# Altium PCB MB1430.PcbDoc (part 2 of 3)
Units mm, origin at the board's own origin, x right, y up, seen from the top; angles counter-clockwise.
Board outline 18.54 x 50.29 mm, 4 copper layers (Top Layer, Signal Layer 1, Signal Layer 2, Bottom Layer), stack 1.614 mm thick; 124 components, 85 nets, 561 pads, 241 vias.
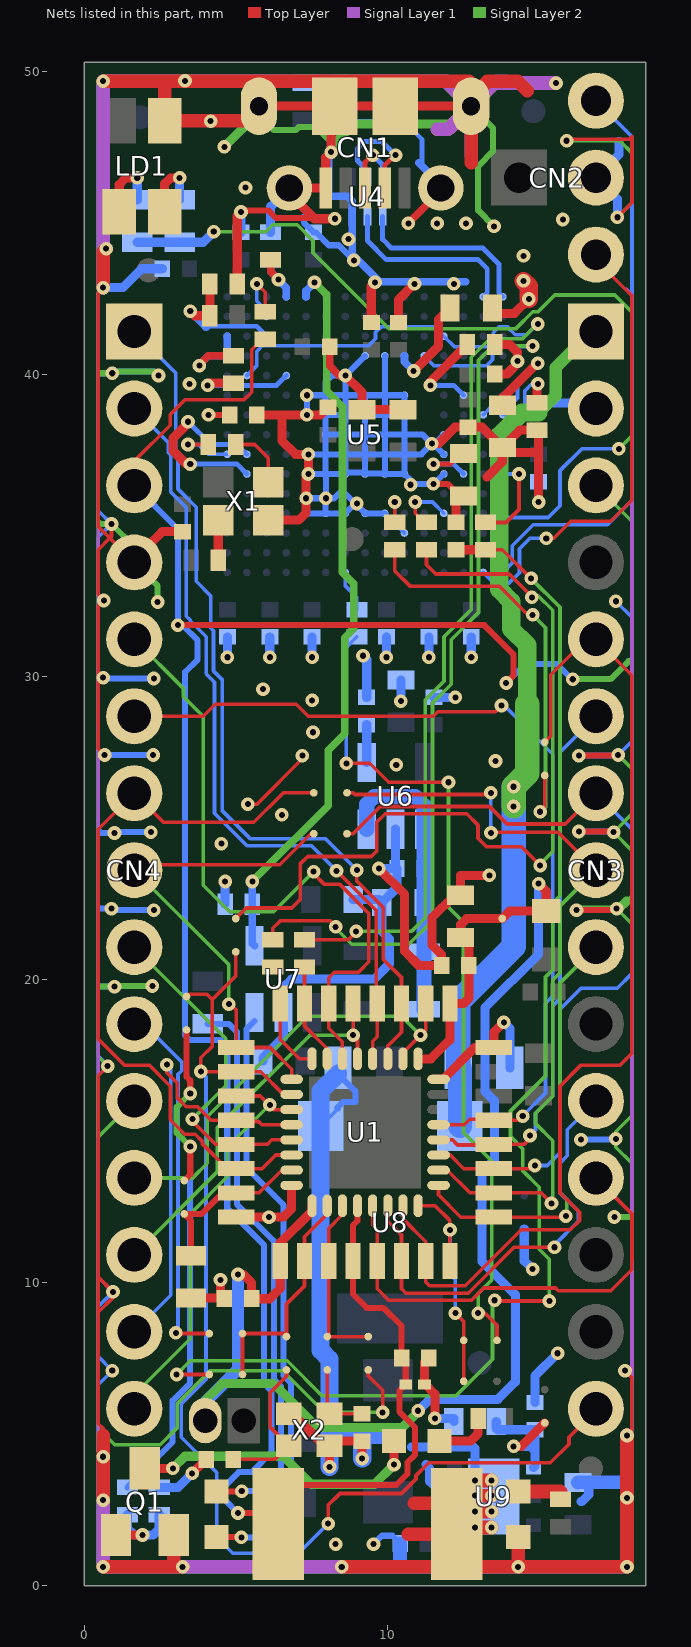
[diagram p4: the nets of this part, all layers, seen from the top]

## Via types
v1: diameter 0.45, hole 0.2, Top Layer to Bottom Layer, tented both sides, 241 vias

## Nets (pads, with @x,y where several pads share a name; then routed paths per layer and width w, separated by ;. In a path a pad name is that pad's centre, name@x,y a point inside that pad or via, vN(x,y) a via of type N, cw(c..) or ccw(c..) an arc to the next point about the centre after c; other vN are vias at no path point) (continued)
GND: B1.2 C1.1 C2.1 C3.1 C4.1 C5.1 C6.1 C7.1 C8.1 C9.1 C10.1 C11.1 C12.1 C13.1 C14.1 C15.1 C16.1 C19.1 C20.1 C21.1 C22.1 C23.1 C24.1 C25.1 C26.1 C27.1 C28.1 C29.1 C30.1 C31.1 C32.1 C33.1 C34.1 C35.1 C36.1 C37.1 C38.1 C39.1 C40.1 C41.1 C42.1 C43.1 C44.1 C45.1 C46.1 C47.1 CN1.5 CN1.6 CN1.7 CN1.8 CN1.9 CN1.10 CN1.11 CN2.3 CN3.2 CN4.4 LD1.1 LD4.2 Q1.2 R2.1 R5.1 R6.1 R7.1 R15.1 R20.1 R22.1 R24.1 SB16.1 U1.16 U1.32 U2.2 U3.2 U4.3 U5.D5 U5.D6 U5.D7 U5.D8 U5.D9 U5.F2 U5.F6 U5.F7 U5.F8 U5.F9 U5.F10 U5.F12 U5.G2 U5.G6 U5.G7 U5.G8 U5.G9 U5.G10 U5.G12 U5.H6 U5.H7 U5.H8 U5.H9 U5.H10 U5.H12 U5.J6 U5.J7 U5.J8 U5.J9 U5.J10 U5.K6 U5.K7 U5.K8 U5.K9 U5.K10 U5.M1 U5.M8 U5.M9 U5.N1 U6.2 U7.2 U8.1 U9.2 U9.EP X1.2 X2.2 X2.4 | length 685.2
  Top Layer w0.12: 0.46,8.825 0.46,10.19 ; 0.625,4.959 0.625,5.192 0.466,5.351 0.466,9.032 0.95,9.516 v1(0.95,9.7) 0.46,10.19 ; v1(0.625,42.85) 0.466,42.691 0.466,34.967 0.846,34.587 ; v1(0.675,27.425) 0.466,27.634 0.466,32.341 v1(0.65,32.525) 0.46,32.715 0.46,34.2 0.846,34.587 ; v1(0.775,17.151) 0.46,16.836 0.46,10.19 ; v1(0.9,35.05) 0.9,34.64 0.846,34.587 ; CN4.4@1.651,33.782 0.846,34.587 ; v1(5.4,25.8) 5.7,25.8 7.2,27.3 v1(7.2,27.4) ; v1(15.925,47.7) 15.975,47.75 18.001,47.75 18.082,47.831 18.082,45.657 v1(17.6,45.175) ; v1(17.85,7.1) 18.076,6.874 18.076,5.118 v1(17.917,4.959)
  Top Layer w0.2: v1(5.175,45.35) 5.225,45.4 6.075,45.4 6.325,45.15 7.575,45.15 8.25,45.15 v1(8.275,45.125) ; X2.4@6.75,5.675 X2.4@6.811,5.675 ; X2.2@8.1,4.625 8.025,4.625 X2.2@8.175,4.775 ; v1(11.526,36.377) 11.998,36.377 12.4,35.975 C12.1@12.525,35.975 ; v1(16.25,22.3) 16.257,22.307 17.532,22.307 v1(17.575,22.35) ; v1(16.325,24.9) 17.45,24.9 v1(17.475,24.875) ; v1(16.325,27.4) 17.6,27.4 v1(17.625,27.425)
  Top Layer w0.25: v1(3.8,40.275) 3.8,40.3 4.1,40.6 R6.1@4.925,40.6 ; C4.1@8.1,40.9 8.1,40.275 8.425,39.95 v1(8.621,39.95) ; v1(10.7,44.975) 11.771,46.046 CN1.6@11.771,46.142
  Top Layer w0.3: CN4.4@1.651,33.782 1.651,33.876 2.575,34.8 C13.1@3.25,34.8 ; v1@3.425,37.025 3.375,37.025 2.93,37.47 2.93,37.88 3.425,38.375 v1(3.425,38.425) ; R15.1@3.525,9.5 C19.1@4.6,9.5 ; v1(3.56,3.71) C22.1@4.025,4.175 ; v1(4.5,10.1) 4.5,9.6 C19.1@4.6,9.5 ; C19.1@4.625,9.475 C19.1@4.6,9.5 ; U1.32@5.025,12.165 U1.32@5.021,12.169 v1(6.1,12.169) 6.569,12.169 6.846,12.446 U1.32@6.846,13.219 ; R2.1@5.05,42.975 5.05,45.225 v1(5.175,45.35) ; C11.1@5.7,38.65 6.525,38.65 ; CN1.8@5.771,48.842 CN1.11@8.271,48.842 CN1.10@10.271,48.842 CN1.9@12.771,48.842 ; X1.2@6.075,35.175 7.075,35.175 7.325,35.425 v1(7.325,35.9) 7.325,36.625 v1(7.4,36.7) v1(7.4,37.35) 6.975,37.35 6.525,37.8 6.525,38.65 ; X2.4@6.811,5.675 6.882,5.675 7.782,4.775 8.175,4.775 C21.1@9.175,4.775 ; C8.1@8.05,38.9 7.8,38.65 v1(7.35,38.65) 6.525,38.65 ; v1(8.1,3.925) X2.2@8.1,4.625 ; CN1.11@8.25,48.8 8.15,48.7 v1(8.15,47.325) 7.971,47.146 CN1.5@7.971,46.142 CN1.7@6.771,46.142 6.771,45.954 7.575,45.15 7.6,45.125 v1(8.275,45.125) ; v1(8.621,39.95) 9.175,39.396 C9.1@9.175,38.825 C10.1@10.525,38.825 ; v1(9.175,4.2) C21.1@9.175,4.775 ; C21.1@9.225,4.825 C21.1@9.175,4.775 ; C2.1@9.475,41.7 9.475,42.9 v1(9.6,43.025) ; v1(9.725,23.675) 10.575,22.825 10.575,20.95 11.05,20.475 C16.1@11.8,20.475 11.8,20.835 11.475,21.16 11.475,22.05 12.225,22.8 C15.1@12.425,22.8 12.425,23.45 v1(13.375,23.45) ; C3.1@10.375,41.7 10.375,42.45 v1(10.9,42.975) ; C20.1@11.375,7.525 11.237,7.387 U2.2@11.237,6.65 11.25,6.65 11.575,6.325 v1(11.575,5.525) ; v1(11.475,37.7) 11.694,37.7 12.244,38.25 C6.1@12.675,38.25 13.125,38.25 C7.1@13.8,37.575 ; U1.16@11.696,16.719 11.844,16.719 12.894,17.769 U1.16@13.521,17.769 13.521,18.271 v1(13.85,18.6) ; C14.1@12.275,35.1 12.275,35.85 C12.1@12.4,35.975 ; 13.3,36.6 13.8,37.1 C7.1@13.8,37.575 ; C1.1@13.475,42.175 13.65,42 14.2,42 v1(14.675,42.475) ; C5.1@13.55,40 13.955,40 14.38,40.425 v1(14.3,40.425) 14.3,40.725 14.05,40.975 R5.1@13.55,40.975 ; v1(15,35.775) 15,37.35 ; C7.1@13.8,37.575 14.375,38.15 R7.1@14.95,38.15 15,38.1 15,37.35 ; C7.1@13.8,37.575 13.963,37.412 14.938,37.412 15,37.35
  Top Layer w0.45: v1(0.625,0.625) 2.95,0.625 ; v1(0.625,2.825) v1(0.625,4.258) 0.625,4.959 ; v1(0.625,42.85) 0.625,44.04 v1(0.725,44.14) ; v1(0.625,49.667) 2.675,49.667 ; Q1.2@2.95,1.675 2.95,0.625 ; v1(3.25,0.625) 2.95,0.625 ; CN1.8@5.771,48.842 5.292,48.363 LD1.1@2.655,48.363 2.655,49.647 2.675,49.667 ; v1(8.5,0.625) 10.221,0.625 ; 10.7,1.7 11.965,1.7 B1.2@12.297,2.032 ; 10.9,2.725 11.604,2.725 B1.2@12.297,2.032 ; 11.253,0.625 10.221,0.625 ; B1.2@12.297,1.669 B1.2@12.297,2.032 ; 12.771,46.979 CN1.9@12.771,48.842 CN1.9@12.771,49.129 ; v1(13.449,1.924) v1(12.899,1.924) 12.405,1.924 B1.2@12.297,2.032 ; v1(13.449,2.449) v1(12.899,2.449) 12.714,2.449 B1.2@12.297,2.032 ; v1(13.449,2.974) v1(12.899,2.974) B1.2@12.399,2.974 ; v1(13.449,3.474) v1(12.899,3.474) B1.2@12.399,2.974 ; LD4.2@14.326,1.612 14.326,0.626 v1(14.325,0.625) ; 14.625,49.35 14.308,49.667 13.309,49.667 CN1.9@12.771,49.129 ; v1(17.917,4.959) v1(17.917,2.9) v1(17.917,0.625) v1(14.325,0.625) ; 2.675,49.667 12.7,49.667 12.771,49.596 CN1.9@12.771,49.129 ; 10.221,0.625 v1(14.325,0.625) ; B1.2@12.297,2.032 12.297,2.872 B1.2@12.399,2.974
  Top Layer w0.6: v1(14.5,43.075) 14.675,42.9 v1(14.675,42.475)
  Signal Layer 1 w0.12: v1(0.625,42.85) 0.46,42.685 0.46,4.44 0.625,4.275 v1@0.642,4.258 ; 17.9,42.8 18.082,42.618 18.082,6.775 18.076,6.769 18.076,5.118 v1(17.917,4.959)
  Signal Layer 1 w0.45: v1@0.625,4.275 v1(0.625,2.825) v1(0.625,0.625) v1(3.25,0.625) v1(8.5,0.625) v1(17.917,0.625) v1(17.917,2.9) v1(17.917,4.959) ; v1(0.625,42.85) v1(0.625,49.667) 11.946,49.667 CN1.9@12.771,48.842 ; 11.65,48.075 12.004,48.075 CN1.9@12.771,48.842 ; v1@15.567,49.608 13.537,49.608 CN1.9@12.771,48.842
  Signal Layer 2 w0.12: v1(0.625,42.85) 0.46,42.685 0.46,32.715 v1(0.65,32.525) 0.466,32.341 0.466,17.46 v1(0.775,17.151) ; v1(15.925,47.7) 17.675,47.7 18.082,47.293 18.082,45.657 v1(17.6,45.175) ; v1(17.575,22.35) 18.076,21.849 ; v1(17.625,27.425) 18.082,26.968 18.082,25.482 v1(17.475,24.875) 18.076,24.274 ; 17.9,22.6 18.076,22.776 ; v1(17.917,4.959) 18.076,5.118 18.076,13.953 17.55,14.479 v1(17.55,14.75) 17.55,14.985 18.076,15.511 18.076,21.849 ; 18.076,21.849 18.076,22.776 ; 18.076,22.776 18.082,22.782 18.082,24.268 18.076,24.274 ; 18.076,22.776 18.076,24.274
  Signal Layer 2 w0.2: 0.5,19.775 v1(1,19.775) 1.025,19.8 v1(2.25,19.8) ; 0.5,35.075 0.525,35.05 v1(0.9,35.05) 1.651,34.299 CN4.4@1.651,33.782 2.425,33.008 v1(2.425,32.475) ; 0.5,40.025 v1(0.925,40.025) 0.987,40.087 2.313,40.087 v1(2.45,39.95) ; CN1.8@5.771,48.842 5.771,48.646 5.771,48.538 6.259,48.05 6.975,48.05 7.075,48.15 7.65,48.15 8.15,47.65 8.15,47.5 v1(8.15,47.325) ; CN1.9@12.771,48.842 13.5,48.113 13.5,47.363 13,46.863 13,45.4 v1(13.525,44.875) ; v1(16.25,22.3) 16.3,22.35 v1(17.575,22.35) ; v1(17.5,12.175) 18.042,12.175
  Signal Layer 2 w0.3: v1(4.625,47.5) CN1.8@5.771,48.646 ; v1@8.15,47.5 8.9,48.25 12.328,48.25 12.771,48.693 CN1.9@12.771,48.842 ; v1(17.575,22.35) 17.65,22.35 17.9,22.6
  Signal Layer 2 w0.45: v1(0.625,4.258) v1(0.625,2.825) v1(0.625,0.625) v1(14.325,0.625) v1(17.917,0.625) v1(17.917,2.9) v1(17.917,4.959) ; v1(0.625,42.85) v1(0.625,49.667) 11.946,49.667 CN1.9@12.771,48.842 12.771,48.921 13.458,49.608 v1@15.567,49.608
  Bottom Layer w0.12: v1@0.46,32.475 0.46,34.61 v1(0.9,35.05) 0.46,35.49 0.46,40.09 ; 0.466,19.775 0.466,32.341 v1(0.65,32.525) ; 0.5,19.775 0.466,19.741 0.466,17.484 ; 0.525,40.025 0.46,40.09 ; v1(0.625,4.258) 0.46,4.423 0.46,6.635 ; v1(0.625,42.85) 0.46,42.685 0.46,40.09 ; v1(0.775,17.151) 0.799,17.151 0.466,17.484 ; U8.1@7.8,15.175 U8.1@8.375,15.75 ; v1(17.55,32.5) 18.082,31.968 18.082,27.882 v1(17.625,27.425) ; v1(17.85,7.1) 18.076,6.874 18.076,5.118 v1(17.917,4.959) ; 0.46,6.635 v1(0.925,7.1) 0.46,7.565 ; 0.46,6.635 0.46,7.565 ; 0.46,7.565 0.46,9.21 0.466,9.216 ; 0.466,9.216 v1(0.95,9.7) 0.466,10.184 ; 0.466,9.216 0.466,10.184 ; 0.466,10.184 0.466,17.484
  Bottom Layer w0.15: v1@8.15,47.55 8.65,48.05 8.7,48.05 9,48.35 10.55,48.35 11.15,47.75 11.15,46.925
  Bottom Layer w0.16: v1@3.425,37.025 5.046,37.025 U5.F2@5.371,36.7 ; v1(3.425,38.425) 4.175,37.675 5.046,37.675 U5.G2@5.371,37.35
  Bottom Layer w0.2: 0.5,19.775 v1(1,19.775) 1.025,19.8 v1(2.25,19.8) ; 0.5,22.375 0.525,22.35 v1(0.9,22.35) 0.943,22.307 2.293,22.307 v1(2.3,22.3) ; 0.5,24.9 0.55,24.85 v1(1,24.85) 1.025,24.875 v1(2.2,24.875) ; 0.525,40.025 v1(0.925,40.025) 0.987,40.087 2.313,40.087 v1(2.45,39.95) ; v1(0.625,29.975) 0.65,29.95 v1(2.3,29.95) ; v1(0.675,27.425) v1(2.275,27.425) ; 7.25,45.192 7.25,45 C24.1@7.575,44.675 7.651,44.675 8.076,44.25 8.4,44.25 v1(8.9,43.75) v1@8.975,43.825 ; v1(8.15,47.325) v1@8.15,47.55 ; U8.1@8.375,15.75 8.35,15.775 8.55,15.975 8.95,15.975 8.95,16.325 8.375,16.9 C42.1@8.375,17.1 ; v1@9,35.75 v1(9,35.727) ; v1(9,35.727) v1@9,35.75 ; U5.M8@9.271,40.6 v1(8.621,39.95) ; v1(9.55,1.375) 9.825,1.65 10.175,1.65 C47.1@10.425,1.4 ; U5.D9@9.921,35.4 U5.D8@9.271,35.4 9,35.671 v1(9,35.727) ; U5.M9@9.921,40.6 U5.K9@9.921,39.3 ; U5.F12@11.871,36.7 11.548,36.377 v1(11.526,36.377) 10.807,36.377 v1(10.775,36.345) 10.775,36.496 U5.F10@10.571,36.7 ; U5.G12@11.871,37.35 v1@11.521,37.7 ; U5.H12@11.871,38 11.571,37.7 v1@11.521,37.7 ; v1(16.25,22.3) 16.257,22.307 17.532,22.307 v1(17.575,22.35) ; v1(16.325,24.9) 17.45,24.9 v1(17.475,24.875) ; v1(16.325,27.4) 17.6,27.4 v1(17.625,27.425) ; v1(16.4,14.725) 17.525,14.725 v1(17.55,14.75) ; v1(7.325,35.9) 7.325,36.625 v1(7.4,36.7) ; v1(7.325,35.9) v1(7.975,35.9) ; v1(7.325,35.9) 7.321,35.896 U5.D5@7.321,35.4 U5.D6@7.971,35.4 ; v1(7.4,36.7) v1(7.4,37.35) U5.G6@7.971,37.35 ; v1(7.4,36.7) U5.F6@7.971,36.7 ; U5.D6@7.971,35.4 U5.D7@8.621,35.4 v1@8.948,35.727 ; U5.D6@7.971,35.4 7.971,35.896 v1(7.975,35.9) ; U5.F6@7.971,36.7 7.975,36.696 v1(7.975,35.9) ; U5.F6@7.971,36.7 U5.G6@7.971,37.35 ; U5.F6@7.971,36.7 U5.F7@8.621,36.7 ; U5.G6@7.971,37.35 U5.G7@8.621,37.35 ; U5.G6@7.971,37.35 U5.H6@7.971,38 ; U5.H6@7.971,38 U5.H7@8.621,38 ; U5.H6@7.971,38 U5.J6@7.971,38.65 ; U5.J6@7.971,38.65 U5.J7@8.621,38.65 ; U5.J6@7.971,38.65 U5.K6@7.971,39.3 ; U5.J6@7.971,38.65 v1(7.35,38.65) v1(7.35,39.3) U5.K6@7.971,39.3 ; U5.K6@7.971,39.3 U5.K7@8.621,39.3 ; U5.K6@7.971,39.3 7.971,39.75 8.171,39.95 v1(8.621,39.95) ; v1(7.975,35.9) 8.25,35.9 8.555,36.205 ; 8.555,36.205 8.555,36.116 8.944,35.727 v1@8.948,35.727 ; 8.555,36.205 8.555,36.634 U5.F7@8.621,36.7 ; U5.F7@8.621,36.7 U5.F7@8.621,36.745 ; U5.F7@8.621,36.745 U5.G7@8.621,37.35 ; U5.F7@8.621,36.745 9.226,36.745 U5.F8@9.271,36.7 U5.F8@9.271,36.72 ; U5.G7@8.621,37.35 U5.G8@9.271,37.35 ; U5.G7@8.621,37.35 U5.H7@8.621,38 ; U5.H7@8.621,38 U5.H8@9.271,38 ; U5.H7@8.621,38 U5.J7@8.621,38.65 ; U5.J7@8.621,38.65 U5.J8@9.271,38.65 ; U5.J7@8.621,38.65 U5.K7@8.621,39.3 ; U5.K7@8.621,39.3 v1(8.621,39.95) ; U5.K7@8.621,39.3 U5.K8@9.271,39.3 ; v1@8.948,35.727 v1(9,35.727) ; U5.F8@9.271,36.72 U5.G8@9.271,37.35 ; U5.F8@9.271,36.72 9.901,36.72 U5.F9@9.921,36.7 ; U5.G8@9.271,37.35 U5.G9@9.921,37.35 ; U5.G8@9.271,37.35 U5.H8@9.271,38 ; U5.H8@9.271,38 U5.H9@9.921,38 ; U5.H8@9.271,38 U5.J8@9.271,38.65 ; U5.J8@9.271,38.65 U5.J9@9.921,38.65 ; U5.J8@9.271,38.65 U5.K8@9.271,39.3 ; U5.K8@9.271,39.3 U5.K9@9.921,39.3 ; U5.F9@9.921,36.7 U5.G9@9.921,37.35 ; U5.F9@9.921,36.7 U5.F10@10.571,36.7 ; U5.G9@9.921,37.35 U5.G10@10.571,37.35 ; U5.G9@9.921,37.35 U5.H9@9.921,38 ; U5.H9@9.921,38 U5.H10@10.571,38 ; U5.H9@9.921,38 U5.J9@9.921,38.65 ; U5.J9@9.921,38.65 U5.J10@10.571,38.65 ; U5.J9@9.921,38.65 U5.K9@9.921,39.3 ; U5.K9@9.921,39.3 U5.K10@10.571,39.3 U5.J10@10.571,38.65 ; U5.F10@10.571,36.7 U5.G10@10.571,37.35 ; U5.G10@10.571,37.35 11.125,37.35 v1(11.475,37.7) ; U5.G10@10.571,37.35 U5.H10@10.571,38 ; U5.H10@10.571,38 11.171,38 11.471,37.7 v1(11.475,37.7) ; U5.H10@10.571,38 U5.J10@10.571,38.65 ; v1(11.475,37.7) v1@11.521,37.7
  Bottom Layer w0.25: v1(3.8,40.275) 3.8,40.3 4.1,40.6 U5.M1@4.721,40.6 U5.N1@4.721,41.25 ; v1(8.15,47.325) 8.075,47.25 8.075,45.875 8.675,45.875 8.85,45.7 U4.3@8.85,45.2 8.85,43.95 8.975,43.825 9.75,43.05 12.6,43.05 ; 11.05,46.98 11.771,46.259 CN1.6@11.771,46.142
  Bottom Layer w0.3: v1(0.625,42.85) 1.275,42.85 1.9,43.475 C26.1@2.575,43.475 ; R24.1@2.475,3.25 3.1,3.25 v1(3.56,3.71) ; R22.1@4.65,22.5 v1(4.65,23.25) ; v1(4.725,30.65) C34.1@4.725,31.325 ; C25.1@5.175,44.675 v1(5.175,45.35) ; C43.1@5.9,17.325 5.9,17.425 6.575,18.1 U7.2@6.575,18.925 6.575,19.75 6.85,20.025 9.575,20.025 10.075,20.525 10.075,21.35 9.825,21.6 C40.1@9.825,22.55 ; v1(6.125,30.65) C33.1@6.125,31.325 ; R20.1@6.15,44.675 6.15,45.521 CN1.7@6.771,46.142 ; v1(7.525,30.65) C32.1@7.525,31.325 ; C39.1@8.875,22.65 9.725,22.65 C40.1@9.825,22.55 ; v1(9.2,30.7) 9.325,30.575 C37.1@9.325,29.325 ; v1(9.725,23.675) C38.1@10.325,23.675 ; v1(9.975,30.65) C31.1@9.975,31.325 ; U6.2@10.275,24.975 10.275,23.725 C38.1@10.325,23.675 ; v1(10.45,29.2) C35.1@10.45,29.9 ; 10.8,4.575 12.85,4.575 12.899,4.526 v1(12.899,3.474) ; 11.275,4 11.4,3.875 11.4,3.45 11.9,2.95 U9.2@12.225,2.95 ; v1(11.375,30.65) C30.1@11.375,31.325 ; C36.1@11.55,29.325 v1(12.25,29.325) ; v1(11.575,5.525) 12.2,5.525 12.163,5.487 12.2,5.45 C45.1@12.2,5.425 ; v1(12.775,30.65) C29.1@12.775,31.325 ; v1(13.85,18.6) 14.05,18.4 C41.1@14.05,17.1 ; SB16.1@14.525,11.775 14.525,10.725 v1(14.8,10.45) ; C44.1@14.875,6.05 14.875,6.925 v1(15.625,7.675) ; v1(15,35.775) C28.1@15,36.45 ; C27.1@15,39.05 16.703,39.05 CN3.2@16.891,38.862 ; 16.4,2.775 16.422,2.775 16.655,3.008 16.655,3.288 C46.1@16.523,3.42 ; v1(17.6,45.175) 17.6,45.773 CN2.3@16.891,46.482 17.65,47.241 17.65,47.675 ; C40.1@9.825,22.55 10.325,23.05 C38.1@10.325,23.675
  Bottom Layer w0.45: v1(0.625,4.258) v1(0.625,2.825) v1(0.625,0.625) 10.375,0.625 ; v1(0.625,42.85) v1(0.625,49.667) C23.1@8.55,49.667 ; C23.1@8.475,49.65 8.533,49.65 C23.1@8.55,49.667 ; C47.1@10.425,1.4 10.425,0.675 10.375,0.625 ; U9.2@12.225,2.95 U9.EP@13.525,2.95 ; 12.771,47.204 CN1.9@12.771,48.842 ; CN1.9@12.771,49.048 CN1.9@12.771,48.9 ; 13.925,49.667 13.596,49.667 CN1.9@12.8,48.871 ; C46.1@16.292,3.408 16.292,3.42 16.523,3.42 17.897,3.42 17.917,3.4 ; v1@17.917,4.925 17.917,3.4 ; C23.1@8.55,49.667 12.004,49.667 CN1.9@12.771,48.9 ; 10.375,0.625 v1(14.325,0.625) v1(17.917,0.625) v1(17.917,2.9) 17.917,3.4 ; CN1.9@12.771,48.842 CN1.9@12.8,48.871 ; CN1.9@12.771,48.842 CN1.9@12.771,48.9 ; CN1.9@12.771,48.9 CN1.9@12.8,48.871
  Bottom Layer w0.6: v1(8.1,3.925) 8.1,4.975 ; C42.1@8.375,16.9 7.8,16.325 U8.1@7.8,15.175 7.8,7.775 8.1,7.475 8.1,4.975 ; v1(9.175,4.2) 9.175,4.95 9.2,4.975 ; 10.225,4.7 9.95,4.975 9.2,4.975 ; 8.1,4.975 9.2,4.975
  other v1: 8.3,1.375 4.525,24.5 6.525,25.45 10.3,27.1 13.575,27.225 7.55,28.175 7.525,29.225 5.9,29.6 3.5,37.025 3.475,39.675 12.2,42.975 14.5,43.9 8.725,44.45 11.65,44.975 12.6,44.975 15.8,45.1 5.325,46.15 4.175,48.35 15.575,49.6 3.325,49.675
GNDDetect: R5.2 U5.K13 | length 3.1
  Top Layer w0.3: v1(11.425,39.625) 11.425,39.75 R5.2@12.65,40.975
  Bottom Layer w0.16: v1(11.425,39.625) 12.196,39.625 U5.K13@12.521,39.3
NetC1_2: C1.2 U5.M10 | length 3.2
  Top Layer w0.3: v1(10.875,40.1) 11.7,40.925 11.7,41.8 C1.2@12.075,42.175
  Bottom Layer w0.25: U5.M10@10.571,40.6 10.571,40.404 v1(10.875,40.1)
NetC7_2: C7.2 U5.J14 | length 4.7
  Top Layer w0.3: C7.2@13.8,38.975 13.8,39.2 14.95,40.35 v1(14.975,40.35)
  Bottom Layer w0.12: U5.J14@13.171,38.65 13.496,38.975 14.075,38.975 14.3,39.2 14.3,39.675 v1(14.975,40.35)
NetC12_2: C12.2 U5.F13 | length 2.3
  Top Layer w0.16: v1(11.525,37.025) 12.075,37.025 12.425,37.375 C12.2@12.525,37.375
  Bottom Layer w0.16: v1(11.525,37.025) 12.196,37.025 U5.F13@12.521,36.7
NetC37_2: C37.2 U6.4 | length 1.3
  Bottom Layer w0.3: U6.4@9.325,27.175 C37.2@9.325,28.425
NetC38_2: C38.2 C40.2 D1.2 D2.2 U6.1 U6.3 | length 9.7
  Bottom Layer w0.5: U6.3@9.325,24.975 9.325,25.8 9.575,26.05 10.925,26.05 11.225,25.75 U6.1@11.225,24.975 C38.2@11.225,23.675 C40.2@11.225,22.55 11.22,22.545 D1.2@11.22,20.925 D2.2@11.22,19.025
NetC44_2: C44.2 C45.2 SB15.1 U9.4 | length 5.1
  Top Layer w0.3: v1(14.175,4.6) 14.425,4.6 SB15.1@15.2,5.375
  Bottom Layer w0.3: C45.2@13.6,5.425 13.6,5.2 13.65,5.15 C44.2@14.875,5.15 14.875,4.75 ; v1@14.175,4.625 v1(14.175,4.6) 14.725,4.6 ; U9.4@14.825,3.9 14.875,3.95 14.875,4.45 ; 14.725,4.6 14.875,4.75 ; 14.725,4.6 14.875,4.45 ; 14.875,4.45 14.875,4.75
NetLD1_2: LD1.2 R18.1 | length 2.2
  Top Layer w0.3: LD1.2@2.655,45.363 2.655,46.28 2.85,46.475 v1(3.15,46.475)
  Bottom Layer w0.3: R18.1@3.15,45.75 v1(3.15,46.475)
NetLD1_3: LD1.3 R19.1 | length 2.3
  Top Layer w0.3: LD1.3@1.155,45.363 1.155,46.255 1.375,46.475 v1(1.75,46.475)
  Bottom Layer w0.3: R19.1@1.75,45.75 v1(1.75,46.475)
NetLD2_1: LD2.1 R16.1 | length 1.9
  Top Layer w0.3: LD2.1@11.725,4.775 12.75,4.775 13,5.025 R16.1@13,5.525
NetLD2_2: LD2.2 Q1.3 | length 9.8
  Top Layer w0.3: Q1.3@2,3.875 v1(2.925,3.875) ; v1(10.225,4) LD2.2@10.225,4.775
  Signal Layer 2 w0.3: v1(2.925,3.875) 3.325,4.275 6.575,4.275 7.5,3.35 9.575,3.35 v1(10.225,4)
NetLD3_1: LD3.1 R23.2 | length 18.6
  Top Layer w0.2: LD3.1@4.369,3.112 5.187,3.112 v1(5.2,3.125)
  Bottom Layer w0.2: R23.2@4.075,18.55 4.775,18.55 5.04,18.285 5.04,12.6 6.26,11.38 6.26,6.812 6.5,6.572 6.5,3.695 5.93,3.125 v1(5.2,3.125)
NetLD3_2: LD3.2 U7.3 | length 19.9
  Top Layer w0.2: LD3.2@4.369,1.612 5.173,1.612 v1(5.185,1.6)
  Bottom Layer w0.2: v1(5.185,1.6) 6.225,1.6 6.82,2.195 6.82,6.705 6.58,6.945 6.58,12.57 5.36,13.79 5.36,18.385 U7.3@5.625,18.65
NetLD4_1: LD4.1 R17.1 | length 1.4
  Top Layer w0.45: LD4.1@14.326,3.112 15.713,3.112 R17.1@15.725,3.1
NetQ1_1: Q1.1 R24.2 R25.2 | length 3
  Top Layer w0.3: Q1.1@1.05,1.675 v1(1.925,1.675)
  Bottom Layer w0.3: R25.2@1.425,2.35 1.425,1.9 1.65,1.675 v1(1.925,1.675) 2.275,1.675 2.475,1.875 R24.2@2.475,2.35
NetR2_2: R2.2 R3.1 U5.N3 | length 4.7
  Top Layer w0.3: v1(3.5,42.075) 3.65,41.925 R3.1@4.15,41.925 R2.2@4.15,42.975
  Bottom Layer w0.16: 4.025,41.575 5.696,41.575 U5.N3@6.021,41.25
  Bottom Layer w0.3: v1(3.5,42.075) 3.5,42.1 4.025,41.575
NetR6_2: R6.2 U5.L4 | length 3.6
  Top Layer w0.3: v1(4.075,39.625) 4.15,39.7 R6.2@4.925,39.7
  Bottom Layer w0.16: v1(4.075,39.625) 6.346,39.625 U5.L4@6.671,39.95
NetR7_2: R7.2 U5.J15 | length 2.5
  Top Layer w0.3: R7.2@14.95,39.05 14.95,39.65 v1(14.975,39.675)
  Bottom Layer w0.12: U5.J15@13.821,38.65 13.821,38.655 14.226,38.655 14.54,38.969 14.54,39.44 14.775,39.675 v1(14.975,39.675)
NetR8_1: R8.1 X1.3 | length 2.1
  Top Layer w0.12: R8.1@5,37.675 5.625,37.675 6.075,37.225 X1.3@6.075,36.425
NetR8_2: R8.2 U5.G1 | length 2.1
  Top Layer w0.12: v1(3.425,37.675) R8.2@4.1,37.675
  Bottom Layer w0.12: v1(3.425,37.675) 3.775,37.675 4.1,37.35 U5.G1@4.721,37.35
NetR11_1: R11.1 U5.F15 | length 3
  Top Layer w0.12: R11.1@13.25,35.1 13.925,35.1 14.35,35.525 v1(14.35,36.7)
  Bottom Layer w0.12: U5.F15@13.821,36.7 v1(14.35,36.7)
NetR12_2: R12.2 X1.1 | length 1.3
  Top Layer w0.3: R12.2@4.425,33.85 X1.1@4.425,35.175
NetR25_1: R25.1 SB6.2 SB7.2 | length 17.6
  Top Layer w0.2: SB7.2@3.3,13.375 3.5,13.575 v1(3.5,14.5) ; SB6.2@3.375,18.35 3.375,16.8 3.5,16.675 v1(3.5,16.25)
  Signal Layer 2 w0.2: v1(3.5,14.5) 3.05,14.95 3.05,15.8 v1(3.5,16.25)
  Bottom Layer w0.2: R25.1@1.425,3.25 2.92,4.745 2.92,6.11 3.495,6.685 3.495,14.495 v1(3.5,14.5)
NetSB8_2: SB8.2 SB9.2 SB13.2 U1.2 | length 7.7
  Top Layer w0.12: SB13.2@5.225,6.975 SB8.2@5.225,8.325 6.575,8.325 SB9.2@6.675,8.225 6.675,9.3 7.271,9.896 U1.2@7.271,10.719 7.271,11.521 8.021,12.271 U1.2@8.021,12.544
NetSB10_2: SB10.2 SB11.2 U1.3 | length 5.8
  Top Layer w0.12: SB10.2@8.025,8.225 SB10.2@8.071,8.271 ; U1.3@8.521,12.544 8.521,12.246 8.071,11.796 U1.3@8.071,10.719 SB10.2@8.071,8.271 ; SB11.2@9.375,8.225 8.117,8.225 SB10.2@8.071,8.271
OSC_IN: C22.2 SB9.1 X2.1 | length 5
  Top Layer w0.12: C22.2@4.925,4.175 6.3,4.175 X2.1@6.75,4.625 6.745,4.625 6.145,5.225 6.145,6.39 6.675,6.92 SB9.1@6.675,7.125
OSC_OUT: C21.2 SB10.1 X2.3 | length 2.6
  Top Layer w0.12: SB10.1@8.025,7.125 8.025,5.75 X2.3@8.1,5.675 C21.2@9.175,5.675
PA0: CN3.12 U1.5 | length 15.4
  Top Layer w0.12: U1.5@9.521,12.544 9.521,11.904 9.675,11.75 9.675,10.723 U1.5@9.671,10.719 9.671,9.804 10.055,9.42 12.774,9.42 13.184,9.83 15.557,9.83 15.65,9.737 17.382,9.737 18.076,10.431 18.076,10.719 18.082,10.725 18.082,12.271 CN3.12@16.891,13.462
PA1: CN3.11 U1.6 | length 14.6
  Top Layer w0.12: U1.6@10.021,12.544 10.021,12.029 10.471,11.579 U1.6@10.471,10.719 10.471,9.804 10.615,9.66 12.674,9.66 14.189,11.175 v1(15.525,11.175)
  Bottom Layer w0.12: v1(15.525,11.175) 15.525,11.252 16.306,12.033 16.306,12.368 15.706,12.968 15.706,13.953 15.946,14.193 15.946,15.057 CN3.11@16.891,16.002
PA2: CN3.5 SB1.2 U1.7 | length 34.8
  Top Layer w0.12: U1.7@10.521,12.544 10.521,12.104 11.271,11.354 U1.7@11.271,10.719 11.271,10.029 11.4,9.9 12.575,9.9 14.425,11.75 16.043,11.75 16.347,12.053 16.347,12.331 15.706,12.971 15.706,16.493 16.4,17.187 17.694,17.187 18.076,17.569 18.076,30.057 CN3.5@16.891,31.242 16.567,31.242 15.4,30.075 15.4,28.05 SB1.2@15.2,27.85
PA3: SB12.2 SB14.2 U1.8 | length 7.8
  Top Layer w0.12: U1.8@11.021,12.544 11.581,12.544 12.071,12.054 U1.8@12.071,10.719 ; v1(12.25,9) 12.525,8.725 SB12.2@12.525,8.1 SB14.2@12.525,6.75
  Bottom Layer w0.12: v1(12.076,11.751) 12.076,10.274 12.25,10.1 v1(12.25,9)
PA4: CN3.9 U1.9 | length 14.4
  Top Layer w0.12: U1.9@11.696,13.219 11.696,12.904 12.431,12.169 U1.9@13.521,12.169 15.869,12.169 v1(15.901,12.201)
  Signal Layer 2 w0.12: v1(15.901,12.201) 15.926,12.175 15.926,12.751 15.706,12.971 15.706,19.897 CN3.9@16.891,21.082
PA5: CN3.8 SB2.1 U1.10 | length 26.6
  Top Layer w0.12: SB2.1@8.675,26.175 8.875,26.175 8.93,26.12 13.37,26.12 v1(13.425,26.175) ; U1.10@11.696,13.719 11.981,13.719 12.731,12.969 U1.10@13.521,12.969 15.081,12.969 v1(15.425,12.625) ; v1(13.426,24.851) 13.45,24.876 15.637,24.876 CN3.8@16.891,23.622
  Signal Layer 2 w0.12: v1(15.425,12.625) 15.425,12.55 15.466,12.591 15.466,14.688 14.896,15.258 14.896,15.594 15.466,16.164 15.466,19.996 15.706,20.236 15.706,22.437 CN3.8@16.891,23.622
  Bottom Layer w0.12: v1@13.425,24.825 v1(13.425,26.175) ; v1@13.426,24.826 v1(13.426,24.851)
PA6: CN3.7 SB3.1 U1.11 | length 27.7
  Top Layer w0.12: SB3.1@8.675,24.825 8.875,24.825 9.775,25.725 13.375,25.725 13.954,25.146 15.875,25.146 CN3.7@16.891,26.162 ; U1.11@11.696,14.219 12.081,14.219 12.531,13.769 U1.11@13.521,13.769 14.769,13.769 v1(14.875,13.875)
  Bottom Layer w0.12: v1(14.875,13.875) 15.289,13.875 15.706,14.292 15.706,19.033 16.4,19.727 17.598,19.727 18.082,20.211 18.082,24.971 CN3.7@16.891,26.162
PA7: CN3.6 U1.12 | length 18
  Top Layer w0.12: U1.12@11.696,14.719 12.156,14.719 12.325,14.55 13.502,14.55 U1.12@13.521,14.569 14.519,14.569 14.75,14.8 14.715,14.835 v1(14.715,14.865)
  Bottom Layer w0.12: v1(14.715,14.865) 14.896,15.046 14.896,15.594 15.466,16.164 15.466,19.132 15.706,19.372 15.706,27.517 CN3.6@16.891,28.702
PA8: CN4.12 U1.18 | length 15
  Top Layer w0.12: U1.18@10.521,17.394 10.521,17.596 v1(11.1,18.175) 11.271,18.346 U1.18@11.271,19.219
  Signal Layer 2 w0.12: CN4.12@1.651,13.462 3.572,13.462 4.06,13.95 4.06,15.485 7.375,18.8 10.475,18.8 v1(11.1,18.175)
PA9: CN4.1 U1.19 | length 29.3
  Top Layer w0.12: v1(9,23.625) 9,23.264 9.875,22.389 9.875,20.675 10.471,20.079 U1.19@10.471,19.219 10.471,18.271 10.021,17.821 U1.19@10.021,17.394
  Bottom Layer w0.12: CN4.1@1.651,41.402 3.02,40.033 3.02,37.5 3.095,37.425 3.095,36.207 3.7,35.602 3.7,33.155 4.18,32.675 4.18,31.61 4.265,31.525 4.265,30.199 4.55,29.914 4.55,25.589 5.474,24.665 7.96,24.665 v1(9,23.625)
PA10: CN4.2 U1.20 | length 26.1
  Top Layer w0.12: v1(8.325,23.6) 9.635,22.29 9.635,19.255 U1.20@9.671,19.219 9.675,19.215 9.675,18.125 9.521,17.971 U1.20@9.521,17.394
  Bottom Layer w0.12: CN4.2@1.651,38.862 2.78,37.733 2.78,37.4 2.855,37.325 2.855,36.108 3.37,35.593 3.37,32.003 3.495,31.878 3.495,31.855 4.025,31.325 4.025,30.1 4.3,29.825 4.3,25.5 5.375,24.425 7.5,24.425 v1(8.325,23.6)
PA11: CN4.13 U1.21 | length 13
  Top Layer w0.12: U1.21@8.871,19.219 8.875,19.215 v1(8.875,18.175) 9.021,18.029 U1.21@9.021,17.394
  Signal Layer 2 w0.12: CN4.13@1.651,10.922 4.385,13.656 4.385,15.11 7.45,18.175 v1(8.875,18.175)
PA12: CN4.5 U1.22 | length 22.1
  Top Layer w0.12: v1(7.575,23.575) 7.575,23.5 7.912,23.163 8.423,23.163 9.395,22.191 9.395,20.595 9.05,20.25 8.25,20.25 8.071,20.071 U1.22@8.071,19.219 8.071,18.404 8.521,17.954 U1.22@8.521,17.394
  Signal Layer 2 w0.12: CN4.5@1.651,31.242 3.275,29.618 3.275,29.347 3.925,28.697 3.925,23.125 4.8,22.25 6.25,22.25 v1(7.575,23.575)
PA15: CN4.8 SB3.2 U1.25 | length 16.2
  Top Layer w0.12: CN4.8@1.651,23.622 1.829,23.8 6.45,23.8 7.475,24.825 SB3.2@7.575,24.825 ; v1(4.775,19.2) 4.775,19.25 5.021,19.004 U1.25@5.021,17.769 6.131,17.769 6.846,17.054 U1.25@6.846,16.719
  Signal Layer 2 w0.12: CN4.8@1.651,23.622 4.775,20.498 v1(4.775,19.2)
PB0: CN4.6 U1.13 | length 30.3
  Top Layer w0.12: CN4.6@1.651,28.702 3.925,28.702 4.323,29.1 7,29.1 7.398,28.702 11.519,28.702 11.672,28.855 13.573,28.855 v1(13.775,29.057) ; U1.13@11.696,15.219 12.544,15.219 12.725,15.4 13.49,15.4 U1.13@13.521,15.369 14.369,15.369 14.5,15.5 v1(14.475,15.5)
  Bottom Layer w0.12: v1(13.775,29.057) 13.862,29.057 15.466,27.453 15.466,19.472 15.226,19.232 15.226,16.263 14.475,15.512 v1(14.475,15.5)
PB3: CN3.15 SB4.1 SB6.1 U1.26 | length 40.5
  Top Layer w0.12: SB6.1@3.375,19.45 3.45,19.525 4.05,19.525 4.225,19.35 ; SB4.1@5,20.925 5,20.125 4.225,19.35 ; U1.26@6.846,16.219 6.581,16.219 5.831,16.969 U1.26@5.021,16.969 3.857,16.969 v1(3.85,16.976) 3.85,17.425 4.225,17.8 4.225,19.35 ; v1(8.05,2.05) 8.05,2.655 8.44,3.045 10.47,3.045 10.95,3.525 10.95,3.64 11.372,4.062 15.387,4.062 16,4.675 16,4.9 16.891,5.791 CN3.15@16.891,5.453
  Bottom Layer w0.12: v1(3.85,16.976) 4.02,16.806 4.02,6.814 3.2,5.994 3.2,4.906 4.37,3.736 4.37,1.611 4.906,1.075 7.075,1.075 v1(8.05,2.05)
PB4: CN4.15 U1.27 | length 13.9
  Top Layer w0.12: U1.27@5.021,16.169 5.806,16.169 v1@6.125,15.85 ; v1(6.125,15.876) v1@6.125,15.85 ; U1.27@6.846,15.719 6.256,15.719 v1@6.125,15.85
  Signal Layer 2 w0.12: CN4.15@1.651,5.842 1.651,6.301 3.5,8.15 3.5,12.275 4.725,13.5 4.725,14.475 v1(6.125,15.876)
PB5: CN4.14 U1.28 | length 14.8
  Top Layer w0.12: v1(2.725,17.201) 2.725,16.943 3.076,16.592 3.076,16.099 3.364,15.811 3.742,15.811 4.183,15.369 U1.28@5.021,15.369 5.065,15.325 5.75,15.325 5.856,15.219 U1.28@6.846,15.219
  Bottom Layer w0.12: CN4.14@1.651,8.382 2.855,9.586 2.855,17.084 v1@2.73,17.209
PB6: CN4.9 U1.29 | length 11.1
  Top Layer w0.12: v1(3.574,15.406) 3.574,15.338 4.343,14.569 U1.29@5.021,14.569 6.044,14.569 6.194,14.719 U1.29@6.846,14.719
  Signal Layer 2 w0.12: CN4.9@1.651,21.082 4.671,18.062 4.671,16.503 v1(3.574,15.406)
PB7: CN4.7 SB2.2 U1.30 | length 24.4
  Top Layer w0.12: U1.30@6.846,14.219 6.319,14.219 5.869,13.769 U1.30@5.021,13.769 4.716,13.769 3.905,14.58 3.905,14.668 3.668,14.905 3.316,14.905 2.836,15.385 2.836,16.493 2.142,17.187 1.324,17.187 0.46,18.051 0.46,24.971 CN4.7@1.651,26.162 2.613,25.2 5.6,25.2 6.575,26.175 SB2.2@7.575,26.175
PB8: R15.2 SB7.1 U1.31 | length 5.6
  Top Layer w0.12: U1.31@5.021,12.969 5.769,12.969 6.519,13.719 U1.31@6.846,13.719
  Top Layer w0.2: R15.2@3.525,10.9 3.525,12.05 SB7.1@3.3,12.275 3.875,12.275 4.569,12.969 U1.31@5.021,12.969
PF0: CN4.10 SB8.1 | length 12.1
  Top Layer w0.12: v1@3.1,8.325 SB8.1@4.125,8.325
  Bottom Layer w0.12: CN4.10@1.651,18.542 1.962,18.542 3.214,17.289 3.214,17 3.095,16.881 3.095,8.42 v1(3.025,8.35)
PF1: CN4.11 SB11.1 | length 24.6
  Top Layer w0.12: SB11.1@9.375,7.125 9.375,6.925 9.85,6.45 v1(9.85,5.725)
  Signal Layer 2 w0.12: CN4.11@1.651,16.002 0.46,14.811 0.46,5.2 1.003,4.657 2.507,4.657 3.075,5.225 3.075,6.025 4.15,7.1 6.55,7.1 7.925,5.725 v1(9.85,5.725)
STLK_LED: R18.2 R19.2 U5.D15 | length 29.1
  Signal Layer 2 w0.12: v1(4.275,44.7) 6,44.7 6.225,44.925 7.027,44.925 7.55,44.402 7.55,44 10.05,41.5 14.252,41.5 14.807,42.055 14.98,42.055 15.533,42.609 17.517,42.609 18.082,42.043 18.082,37.964 v1(17.647,37.529)
  Bottom Layer w0.12: U5.D15@13.821,35.4 13.956,35.265 15.315,35.265 15.706,35.656 15.706,36.813 16.422,37.529 v1(17.647,37.529)
  Bottom Layer w0.3: R19.2@1.75,44.35 R18.2@3.15,44.35 3.925,44.35 v1(4.275,44.7)
STLK_MCO: C14.2 R11.2 SB13.1 | length 44.8
  Top Layer w0.12: v1(3.05,6.975) SB13.1@4.125,6.975 ; R11.2@13.25,34.2 13.803,34.2 v1(14.75,33.253) ; v1(13.55,9.425) 13.575,9.4 v1(15.353,9.4)
  Top Layer w0.3: C14.2@12.275,34.2 R11.2@13.25,34.2
  Signal Layer 2 w0.12: v1(3.05,6.975) 3.5,7.425 6.7,7.425 7.85,6.275 12.275,6.275 13.475,7.475 13.475,9.35 v1(13.55,9.425) ; v1@14.773,33.275 v1(14.75,33.253) 15.706,32.297 15.706,22.776 15.466,22.536 15.466,20.336 15.226,20.096 15.226,16.826 14.07,15.67 14.07,14.83 14.47,14.43 14.47,13.707 15.02,13.157 15.02,11.107 15.353,10.775 v1(15.353,9.4)
STLK_RST: C11.2 U5.J1 | length 1.3
  Top Layer w0.2: v1(4.1,38.65) C11.2@4.8,38.65
  Bottom Layer w0.2: v1(4.1,38.65) U5.J1@4.721,38.65
STLK_SWCLK: CN2.4 U5.A14 | length 15.2
  Top Layer w0.12: v1(15.251,34.577) 15.499,34.577 16.059,35.137 17.382,35.137 18.076,35.831 18.076,42.587 16.891,43.772 CN2.4@16.891,43.942
  Bottom Layer w0.12: U5.A14@13.171,33.45 13.521,33.1 14.025,33.1 14.366,33.441 14.366,34.229 14.714,34.577 v1(15.251,34.577)
STLK_SWDIO: CN2.2 U5.A15 | length 19.3
  Bottom Layer w0.12: U5.A15@13.821,33.45 14.123,33.752 14.123,33.968 14.126,33.971 14.126,34.328 14.823,35.025 17.27,35.025 18.082,35.837 18.082,47.831 CN2.2@16.891,49.022
STLK_VCP_RX: R9.2 U5.C10 | length 1.8
  Top Layer w0.12: R9.2@10.25,35.1 v1(10.25,35.775)
  Bottom Layer w0.12: v1(10.25,35.775) 10.25,35.071 U5.C10@10.571,34.75
STLK_VCP_TX: R21.1 U5.A7 | length 1.4
  Bottom Layer w0.12: U5.A7@8.621,33.45 8.621,33.004 9,32.625 R21.1@9,32.225
T_NRST: B1.1 C20.2 CN3.3 CN4.3 R4.1 U1.4 U2.1 | length 86.9
  Top Layer w0.12: CN4.3@1.651,36.322 1.651,37.126 2.836,38.311 2.836,38.661 3.325,39.15 5.275,39.15 5.525,39.4 5.525,40.8 5.875,41.15 R4.1@5.975,41.15
  Top Layer w0.2: v1(3.09,31.71) 13.205,31.71 14.175,30.74 14.175,30.05 v1(13.925,29.8) ; v1(5.075,2.4) 6.375,2.4 6.397,2.378 B1.1@6.397,2.032 6.65,2.285 6.65,3.325 10.3,3.325 10.67,3.695 10.67,4.07 10.925,4.325 10.925,5.225 10.4,5.75 10.4,6.437 U2.1@10.613,6.65 10.613,7.387 C20.2@10.475,7.525 10.475,8.575 9.875,9.175 9.325,9.175 8.871,9.629 U1.4@8.871,10.719 8.871,11.896 9.021,12.046 U1.4@9.021,12.544
  Signal Layer 2 w0.12: CN3.3@16.891,36.322 18.076,35.137 18.076,30.626 17.975,30.525
  Signal Layer 2 w0.2: v1(16.125,29.925) 16.127,29.927 17.377,29.927 17.975,30.525
  Bottom Layer w0.2: CN4.3@1.651,36.322 3.09,34.883 v1(3.09,31.71) 3.244,31.71 3.745,31.209 3.745,30.575 3.325,30.155 3.325,18.169 3.484,18.01 4.49,18.01 4.72,17.78 4.72,12.467 5.94,11.247 5.94,6.68 6.18,6.44 6.18,4.4 5.53,3.75 5.1,3.75 4.65,3.3 4.65,2.825 v1(5.075,2.4) ; v1(13.925,29.8) 14.55,30.425 15.6,30.425 16.1,29.925 v1(16.125,29.925)
T_NRSTa: R4.2 U5.P3 | length 2.2
  Top Layer w0.12: v1(5.7,42.975) 5.975,42.7 R4.2@5.975,42.05
  Bottom Layer w0.12: v1(5.7,42.975) 5.7,42.4 6.021,42.079 U5.P3@6.021,41.9
T_PWR_EN: R22.2 U5.R5 U7.4 | length 24.4
  Signal Layer 2 w0.25: v1(5.55,23.25) 8.05,25.75 8.05,27.575 8.6,28.125 8.6,31.3 8.9,31.6 8.9,33.075 8.525,33.45 8.525,38.925 8,39.45 8,42.625 v1(7.6,43.025)
  Bottom Layer w0.25: v1(5.55,23.25) R22.2@5.55,22.5 5.55,21.2 U7.4@5.625,21.125 ; U5.R5@7.321,42.55 7.321,42.746 v1(7.6,43.025)
T_PWR_EXT: R1.1 R20.2 U5.R4 | length 2.2
  Top Layer w0.25: R1.1@6.15,43.775 6.15,43.375 v1(6.411,43.114)
  Bottom Layer w0.25: R20.2@6.15,43.775 6.15,43.375 v1(6.411,43.114) 6.671,42.854 U5.R4@6.671,42.55
T_SWCLK: R13.1 U1.24 | length 3.8
  Top Layer w0.12: R13.1@6.225,20.425 6.471,20.179 U1.24@6.471,19.219 6.471,18.029 7.106,17.394 U1.24@7.521,17.394
T_SWCLKa: R13.2 U5.M11 | length 31.6
  Top Layer w0.12: R13.2@6.225,21.325 6.225,21.7 6.475,21.95 8.125,21.95 8.3,21.775 v1(8.3,21.751)
  Signal Layer 2 w0.12: v1(8.3,21.751) 8.3,21.702 8.827,21.175 10.714,21.175 11.495,21.956 11.495,29.143 12.115,29.763 12.115,31.226 13.015,32.126 13.015,40.451 13.489,40.925 v1(14.8,40.925)
  Bottom Layer w0.12: U5.M11@11.221,40.6 11.546,40.275 13.277,40.275 13.476,40.474 13.476,40.686 13.695,40.905 14.78,40.905 v1(14.8,40.925)
T_SWDIO: R14.1 U1.23 | length 3.3
  Top Layer w0.12: R14.1@7.275,20.425 7.271,20.421 U1.23@7.271,19.219 7.271,18.479 8.021,17.729 U1.23@8.021,17.394
T_SWDIOa: R14.2 U5.L2 U5.N12 | length 37.7
  Top Layer w0.12: R14.2@7.275,21.325 8.725,21.325 8.975,21.575 v1(8.975,21.6)
  Signal Layer 2 w0.12: v1(8.975,21.6) 10.8,21.6 11.255,22.055 11.255,29.242 11.875,29.862 11.875,31.325 12.775,32.225 12.775,40.55 13.39,41.165 14.467,41.165 14.952,41.65 v1(14.975,41.65)
  Bottom Layer w0.12: U5.L2@5.371,39.95 5.7,40.279 5.7,40.75 5.88,40.93 9.382,40.93 9.616,41.164 9.616,41.376 9.795,41.555 11.566,41.555 U5.N12@11.871,41.25 12.216,40.905 13.297,40.905 13.302,40.9 13.35,40.9 13.5,41.05 13.5,41.36 13.695,41.555 13.97,41.555 14.225,41.3 14.602,41.3 14.952,41.65 v1(14.975,41.65)
T_SWO: R10.1 SB4.2 | length 27.7
  Top Layer w0.12: SB4.2@5,22.025 5.35,22.375 6.85,22.375 7.125,22.65 7.125,23.825 7.375,24.075 9.475,24.075 9.65,24.25 9.65,25.2 9.935,25.485 12.625,25.485 13,25.11 13,24.675 13.275,24.4 14.425,24.4 v1(15.05,23.775) ; R10.1@11.3,34.2 11.3,33.7 11.6,33.4 14.03,33.4 14.78,32.65 14.776,32.645 v1(14.776,32.627)
  Signal Layer 2 w0.12: v1(14.776,32.627) 14.825,32.676 14.988,32.676 15.466,32.198 15.466,24.241 15.025,23.8 v1(15.05,23.775)
T_SWOa: R10.2 U5.D12 | length 2
  Top Layer w0.12: v1(10.925,35.775) 10.925,35.4 11.225,35.1 R10.2@11.3,35.1
  Bottom Layer w0.12: v1(10.925,35.775) 11.496,35.775 U5.D12@11.871,35.4
T_VCP_RX: R21.2 SB12.1 | length 27.5
  Top Layer w0.12: v1(8.65,27.15) 9.425,27.15 10.05,26.525 v1(12.025,26.525) ; v1(13.001,9) 13.227,9 13.625,8.602 SB12.1@13.625,8.1
  Signal Layer 2 w0.12: v1(12.025,26.525) 12.025,22.4 12.519,21.906 12.519,14.956 13.45,14.025 13.45,10.096 13.001,9.647 v1(13.001,9)
  Bottom Layer w0.12: v1(8.65,27.15) 8.65,30.975 R21.2@9,31.325
T_VCP_TX: R9.1 SB1.1 | length 13.9
  Top Layer w0.12: R9.1@10.25,34.2 10.25,33.5 10.75,33 13.7,33 14.675,32.025 14.775,32.025 v1(14.801,32.052) ; v1(15.051,25.551) 15.2,25.701 SB1.1@15.2,26.75
  Signal Layer 2 w0.12: v1(14.801,32.052) 15.226,31.626 15.226,25.701 15.075,25.55 15.074,25.551 v1(15.051,25.551)
USB_DEV_HS_CN_N: CN1.2 U4.5 | length 3.9
  Top Layer w0.16: CN1.2@9.921,46.142 9.921,46.896 10.25,47.225 v1(10.275,47.225)
  Bottom Layer w0.16: U4.5@9.35,46.5 9.35,46.7 9.175,46.875 9.175,46.883 9.025,47.033 9.025,47.45 9.25,47.675 9.825,47.675 v1(10.275,47.225)
USB_DEV_HS_CN_P: CN1.3 U4.6 | length 2.3
  Top Layer w0.16: CN1.3@9.271,46.142 9.271,46.996 9.513,47.238 v1@9.525,47.25 ; v1(9.525,47.225) v1@9.525,47.25 ; v1@9.525,47.25 9.525,47.35 9.575,47.3 v1@9.525,47.25
  Bottom Layer w0.16: v1(9.525,47.225) 9.85,46.9 U4.6@9.85,46.5
USB_DEV_HS_N: U4.2 U5.R14 | length 6.1
  Bottom Layer w0.16: U4.2@9.35,45.2 9.35,44.4 9.975,43.775 13,43.775 13.303,43.472 13.303,42.682 U5.R14@13.171,42.55
USB_DEV_HS_P: U4.1 U5.R15 | length 6.1
  Bottom Layer w0.16: U4.1@9.85,45.2 9.85,44.446 10.135,44.161 13.16,44.161 13.689,43.632 13.689,42.682 U5.R15@13.821,42.55
VDD: C15.2 C16.2 C19.2 JP1.2 L1.2 SB5.2 U1.1 U1.17 | length 51.6
  Top Layer w0.3: v1(5.075,10.275) 5.25,10.275 5.525,10 C19.2@5.525,9.475 6.125,9.475 6.471,9.821 U1.1@6.471,10.719 6.471,11.321 7.521,12.371 U1.1@7.521,12.544 ; U1.17@11.021,17.394 11.444,17.394 12.071,18.021 U1.17@12.071,19.219 12.519,19.219 12.7,19.4 C16.2@12.7,20.475 12.7,21.125 C15.2@12.425,21.4 12.425,21.825 12.625,22.025 SB5.2@13.8,22.025 14.05,22.275 L1.2@15.25,22.275 15.25,22.925 v1(15,23.175)
  Signal Layer 2 w0.3: JP1.2@3.995,5.45 3.995,6.12 4.55,6.675 6.25,6.675 7.695,5.23 10.505,5.23 11.025,5.75 11.025,5.775 v1(11.022,5.778)
  Bottom Layer w0.3: v1(11.022,5.778) 11.025,5.775 11.4,6.15 13.65,6.15 14.23,6.73 14.23,9.605 13.125,10.71 13.125,13.644 13.54,14.059 13.54,16.01 13.225,16.325 13.225,19.075 15,20.85 v1(15,23.175)
  Bottom Layer w0.4: v1(5.075,10.275) 5.075,7.145 JP1.2@4.046,6.116 ; JP1.2@4.046,6.116 4.046,5.509 4.046,5.45 JP1.2@3.995,5.45 3.995,5.56 3.995,6.065 JP1.2@4.046,6.116
  Bottom Layer w0.5: JP1.2@3.95,5.605 3.995,5.56 4.046,5.509 JP1.2@4.105,5.45
VIN: C41.2 CN3.1 U8.3 | length 29.9
  Signal Layer 2 w0.4: 15,38.725 15.566,39.291 15.566,40.216 16.752,41.402 CN3.1@16.891,41.402
  Signal Layer 2 w0.6: 14.625,29.1 14.625,31.05 14.095,31.58 14.095,32.492 13.7,32.887 13.7,37.975 14.45,38.725 15,38.725
  Signal Layer 2 w0.8: v1(14.175,25.729) v1(14.175,26.375) 14.625,26.825 14.625,29.1
  Bottom Layer w0.8: U8.3@12.4,15.175 12.4,17.05 C41.2@12.35,17.1 12.35,19.275 14.175,21.1 v1(14.175,25.729) v1(14.175,26.375)
pads on no net: CART1.1 CN1.4 MP1.1 MP2.1 MP3.1 MP4.1 MP5.1 MP6.1 U1.33 U4.4 U5.A1 U5.A2 U5.A3 U5.A4 U5.A5 U5.A6 U5.A8 U5.A9 U5.A10 U5.A11 U5.A12 U5.A13 U5.B1 U5.B2 U5.B3 U5.B4 U5.B5 U5.B6 U5.B7 U5.B8 U5.B9 U5.B10 U5.B11 U5.B12 U5.B13 U5.B14 U5.B15 U5.C2 U5.C3 U5.C4 U5.C11 U5.C12 U5.C13 U5.C14 U5.C15 U5.D1 U5.D2 U5.D3 U5.D4 U5.D10 U5.D11 U5.D13 U5.D14 U5.E1 U5.E2 U5.E3 U5.E4 U5.E12 U5.E13 U5.E14 U5.E15 U5.F1 U5.F4 U5.F14 U5.G4 U5.G14 U5.G15 U5.H1 U5.H2 U5.H3 U5.H4 U5.H14 U5.H15 U5.J2 U5.J3 U5.J4 U5.K1 U5.K2 U5.K3 U5.K12 U5.K14 U5.K15 U5.L1 U5.L3 U5.L12 U5.L13 U5.L14 U5.L15 U5.M2 U5.M3 U5.M4 U5.M5 U5.M6 U5.M7 U5.M12 U5.M13 U5.M14 U5.M15 U5.N2 U5.N4 U5.N5 U5.N6 U5.N7 U5.N11 U5.N13 U5.N14 U5.N15 U5.P2 U5.P4 U5.P5 U5.P6 U5.P7 U5.P8 U5.P9 U5.P10 U5.P11 U5.P12 U5.P13 U5.P14 U5.P15 U5.R2 U5.R3 U5.R6 U5.R7 U5.R8 U5.R9 U5.R10 U5.R11 U5.R12 U5.R13 U9.3 U9.5

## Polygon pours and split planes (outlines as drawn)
3V3_STLK on Signal Layer 2 "3V3_STLK_L03_P010" (solid, remove dead copper, pour order 10): 2.45,47.75 1.85,47.15 1.85,32.975 3.05,31.775 6.15,31.775 7.15,30.775 8.525,30.775 8.9,30.4 8.9,27.95 9.5,27.35 10.98,27.35 11.275,27.645 11.275,29.45 12.775,30.95 12.775,40.45 12.125,41.1 10.075,41.1 4.775,46.4 4.775,47.325 4.35,47.75
GND on Signal Layer 2 "GND_L03_P012" (solid, remove dead copper, pour order 12): 0.025,50.275 0.025,0.025 18.525,0.025 18.525,50.275
GND on Signal Layer 1 "GND_L02_P006" (solid, remove dead copper, pour order 6): 0.1,50.175 0.1,0.1 18.45,0.1 18.45,50.175
GND on Top Layer "GND_L01_P008" (solid, remove dead copper, pour order 8): 0.025,50.275 18.525,50.275 18.525,0.025 0.025,0.025
GND on Bottom Layer "GND_L04_P014" (solid, remove dead copper, pour order 14): 0.025,50.25 18.525,50.25 18.525,0.025 0.025,0.025

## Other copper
Top Layer:
  text "1" at 5,28.8 h1.3 r270
Signal Layer 1:
  text "2" at 5,28.3 h1.3 r270
Signal Layer 2:
  text "3" at 5,27 h1.3 r270
Bottom Layer:
  pour cut-out: 6.325,35.575 6.825,35.075 11.9,35.075 12.225,35.4 12.225,40.896 11.566,41.555 11.561,41.55 6.625,41.55 6.325,41.25
  text "4" at 5,26.2 h1.3 r270
Multi-Layer:
  pour cut-out: 4.8,26.1 6,26.1 6,28.9 4.8,28.9

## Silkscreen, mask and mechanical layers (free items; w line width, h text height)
Top Overlay:
  drawing of 2338 lines, arcs and shapes, not listed
  text "COM" at 0.725,49.35 h1.2
  text "RSV" at 13.475,49.325 h1.2
  text "USB STLK" at 4.975,45.025 h1.2 r90
  text "1" at 0.275,41.075 h1.2
  text "1" at 17.95,41.075 h1.2
  text "D1" at 0.575,39.125 h1.2 r45
  text "D0" at 0.7,36.75 h1.2 r45
  text "25MHz" at 7.525,33.65 h1.2 r90
  text "A7" at 17.575,29.45 h1.2 r45
  text "D2" at 0.675,29.125 h1.2 r45
  text "MB1430A" at 15.15,29.025 h1.7 r90
  text "A6" at 17.575,26.9 h1.2 r45
  text "D3" at 0.675,26.6 h1.2 r45
  text "CN4" at 3.4,26.375 h1.2 r90
  text "A5" at 17.55,24.35 h1.2 r45
  text "D4" at 0.725,24.1 h1.2 r45
  text "A4" at 17.575,21.8 h1.2 r45
  text "D5" at 0.675,21.5 h1.2 r45
  text "A3" at 17.575,19.275 h1.2 r45
  text "D6" at 0.65,18.975 h1.2 r45
  text "A2" at 17.6,16.75 h1.2 r45
  text "D7" at 0.65,16.4 h1.2 r45
  text "A1" at 17.625,14.2 h1.2 r45
  text "D8" at 0.675,13.9 h1.2 r45
  text "A0" at 17.625,11.675 h1.2 r45
  text "D9" at 0.675,11.35 h1.2 r45
  text "CN3" at 15.95,11.125 h1.2 r90
  text "9" at 6.425,9.025 h1.2
  text "10" at 7.5,9.025 h1.2
  text "11" at 8.875,9.025 h1.2
  text "10" at 0.775,9 h1.2 r45
  text "8" at 2.725,7.925 h1.2
  text "13" at 2.2,6.625 h1.2
  text "11" at 0.775,6.575 h1.2 r45
  text "12" at 0.625,4.025 h1.2 r45
  text "D13" at 18.35,3.225 h1.2 r90
  text "5V" at 14.8,0.825 h1.2
  text "PWR" at 16.125,0.825 h1.2
  text "OC" at 1.825,0.075 h1.2
  text "RESET" at 14.575,0.025 h1.2
Bottom Overlay:
  region: 3.625,6.325 3.625,13.65 3.125,13.65 3.125,6.325
  region: 7.15,6.325 7.15,9.95 6.65,9.95 6.65,6.325
  rectangle: 3.125,6.323 7.15,6.823
  rectangle: 3.125,13.15 6.55,13.65
  lines w0.12: 4.05,31.05 4.2,30.9 11.325,30.9 11.35,30.925 11.375,30.95 ; 5.15,45.45 5.7,45.45 6.025,45.125 ; 5.275,45.975 5.275,45.7 5.925,45.7 ; 5.275,46.5 5.275,46.975 ; 5.275,47.475 5.275,47.95 ; 5.275,49.7 5.275,50.175 ; 6.3,28.525 6.45,28.675 7.075,28.675 8.6,28.675 8.725,28.8 8.75,28.825 8.75,29.7 9.525,30.475 11.5,30.475 11.9,30.075 11.9,29.825 ; 7.675,45.7 8.15,45.7 ; 7.9,24.45 7.9,24.275 8.625,23.55 9.375,23.55 9.65,23.275 ; 7.9,25.25 7.9,25.1 9.175,23.825 9.85,23.825 ; 10.5,45.7 10.975,45.7 ; 12.575,45.7 13.05,45.7 13.25,45.7 13.275,45.725 13.275,46.025 ; 13.075,45.5 13.075,45.325 13.775,45.325 ; 13.275,46.5 13.275,46.975 ; 13.275,47.475 13.275,47.95 ; 13.275,49.7 13.275,50.175 ; 13.475,47.675 13.775,47.675 ; 14.15,45.325 14.7,45.325 ; 14.15,47.675 14.7,47.675 ; 15.075,45.325 15.625,45.325 15.625,45 ; 15.075,47.675 15.625,47.675 15.625,48.325 ; 15.625,42.675 15.625,43.225 ; 15.625,43.15 15.625,43.7 ; 15.625,44.075 15.625,44.625 ; 15.625,48.7 15.625,49.25 ; 15.625,49.625 15.625,50.175 ; 18.15,42.675 18.15,43.25 ; 18.15,43.15 18.15,43.7 ; 18.15,44.075 18.15,44.625 ; 18.15,45 18.15,45.55 ; 18.15,45.925 18.15,46.475 ; 18.15,46.85 18.15,47.4 ; 18.15,47.775 18.15,48.325 ; 18.15,48.7 18.15,49.25 ; 18.15,49.625 18.15,50.175
  text "1" at 13.975,44.725 h1.5 r270
  text "www.st.com/stm32nucleo" at 3.075,27.025 h1.3 r270
  text "RoHS" at 5.725,6.925 h1.2 r270
  text "2002/95/EC" at 3.75,6.9 h1.2 r270
  text "COMPLIANT" at 4.75,6.9 h1.2 r270
  text "IDD" at 7.325,0.2 h1.2
Top Solder:
  region: 6,26.1 6,28.9 4.8,28.9 4.8,26.1
Bottom Solder:
  region: 6,26.1 6,28.9 4.8,28.9 4.8,26.1
M1-Board Shape:
  lines w0.1: 0,0 0,50.292 0.147,50.292 18.308,50.292 18.542,50.292 18.542,50.193 18.542,0 18.438,0 0,0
